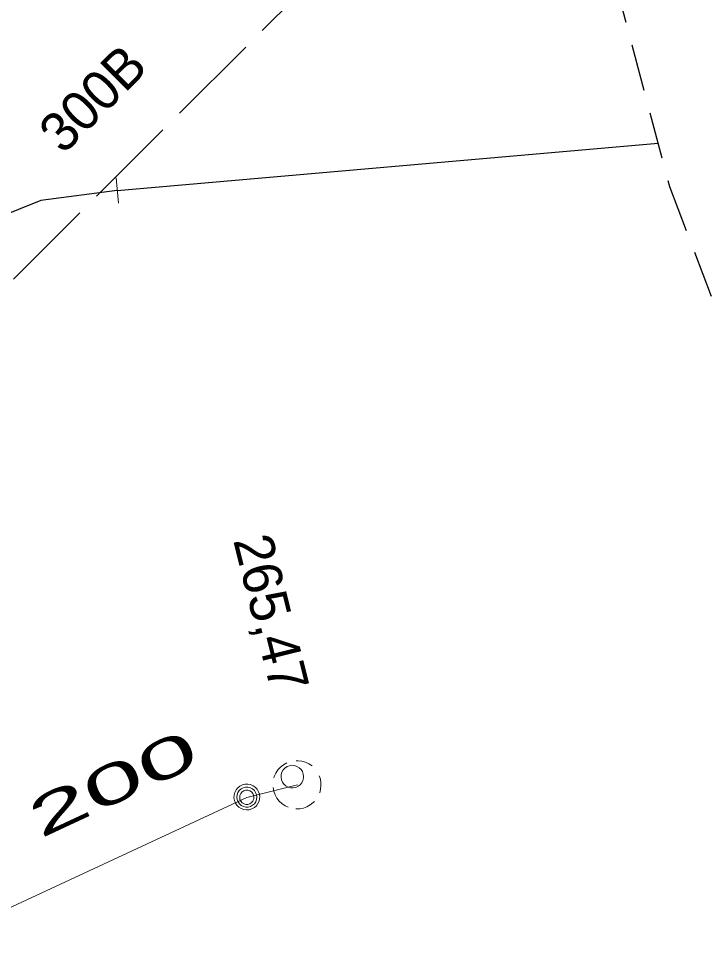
# Model space of a CAD drawing. Extents: x -732074 to -731966, y -1048695 to -1047982.
# Drawn here: x -732034.06 to -732020.02, y -1048482.15 to -1048462.87 of the extents above; entities that cross this region are included whole.
import ezdxf

# ---------------------------------------------------------------- set-up
doc = ezdxf.new("R2010")
doc.units = 0
doc.header["$LTSCALE"] = 0.32
doc.linetypes.add('LONG_DASHED', pattern=[7.5, 6, -1.5])
doc.linetypes.add('MEDIUM_DASHED', pattern=[4.5, 3, -1.5])
doc.layers.add('1', color=7, linetype='Continuous')
for name, color, linetype, lineweight in [('18', 7, 'Continuous', 13), ('20', 7, 'Continuous', 13), ('49', 7, 'Continuous', 13), ('63', 7, 'MEDIUM_DASHED', 25), ('8', 7, 'Continuous', 13)]:
    doc.layers.add(name, color=color, linetype=linetype, lineweight=lineweight)

msp = doc.modelspace()

# ---------------------------------------------------------------- linework, layer by layer
at = {"layer": '18'}
for points in [[(-732028.583, -1048478.109), (-732028.649, -1048478.148), (-732028.71, -1048478.196), (-732028.762, -1048478.252), (-732028.804, -1048478.316), (-732028.836, -1048478.387), (-732028.845, -1048478.412)], [(-732028.064, -1048478.171), (-732028.127, -1048478.129), (-732028.197, -1048478.096), (-732028.271, -1048478.073), (-732028.347, -1048478.064), (-732028.388, -1048478.063)], [(-732027.908, -1048478.721), (-732027.889, -1048478.647), (-732027.881, -1048478.571), (-732027.884, -1048478.494), (-732027.9, -1048478.419), (-732027.916, -1048478.371)], [(-732028.862, -1048478.615), (-732028.848, -1048478.69), (-732028.821, -1048478.763), (-732028.784, -1048478.829), (-732028.736, -1048478.89), (-732028.68, -1048478.942), (-732028.616, -1048478.985), (-732028.553, -1048479.015)], [(-732028.394, -1048479.049), (-732028.317, -1048479.046), (-732028.242, -1048479.032), (-732028.169, -1048479.005), (-732028.102, -1048478.968), (-732028.042, -1048478.921), (-732028.016, -1048478.896)]]:
    msp.add_lwpolyline(points, dxfattribs=at)
for points in [[(-732028.238, -1048478.389), (-732028.244, -1048478.337), (-732028.262, -1048478.287), (-732028.29, -1048478.243), (-732028.328, -1048478.206), (-732028.373, -1048478.179), (-732028.423, -1048478.163), (-732028.475, -1048478.158), (-732028.527, -1048478.165), (-732028.576, -1048478.184), (-732028.62, -1048478.214), (-732028.655, -1048478.253), (-732028.681, -1048478.298), (-732028.696, -1048478.349), (-732028.699, -1048478.401), (-732028.691, -1048478.453), (-732028.67, -1048478.501), (-732028.64, -1048478.544), (-732028.6, -1048478.579), (-732028.554, -1048478.603), (-732028.503, -1048478.617), (-732028.451, -1048478.619), (-732028.399, -1048478.609), (-732028.351, -1048478.587), (-732028.309, -1048478.555), (-732028.276, -1048478.515), (-732028.252, -1048478.468), (-732028.24, -1048478.417)], [(-732029.135, -1048478.807), (-732029.141, -1048478.751), (-732029.157, -1048478.698), (-732029.186, -1048478.649), (-732029.225, -1048478.608), (-732029.271, -1048478.576), (-732029.323, -1048478.554), (-732029.378, -1048478.543), (-732029.434, -1048478.545), (-732029.489, -1048478.558), (-732029.539, -1048478.583), (-732029.584, -1048478.618), (-732029.62, -1048478.661), (-732029.645, -1048478.711), (-732029.66, -1048478.766), (-732029.663, -1048478.822), (-732029.654, -1048478.877), (-732029.633, -1048478.93), (-732029.602, -1048478.976), (-732029.561, -1048479.015), (-732029.514, -1048479.045), (-732029.461, -1048479.064), (-732029.405, -1048479.071), (-732029.348, -1048479.067), (-732029.294, -1048479.05), (-732029.245, -1048479.023), (-732029.204, -1048478.985), (-732029.171, -1048478.94), (-732029.147, -1048478.889), (-732029.136, -1048478.834)], [(-732029.194, -1048478.81), (-732029.2, -1048478.761), (-732029.218, -1048478.715), (-732029.245, -1048478.674), (-732029.282, -1048478.641), (-732029.326, -1048478.619), (-732029.375, -1048478.607), (-732029.424, -1048478.607), (-732029.472, -1048478.619), (-732029.516, -1048478.642), (-732029.553, -1048478.675), (-732029.581, -1048478.716), (-732029.598, -1048478.763), (-732029.603, -1048478.812), (-732029.597, -1048478.861), (-732029.579, -1048478.907), (-732029.551, -1048478.947), (-732029.514, -1048478.98), (-732029.47, -1048479.002), (-732029.421, -1048479.014), (-732029.372, -1048479.013), (-732029.324, -1048479.001), (-732029.281, -1048478.977), (-732029.244, -1048478.944), (-732029.216, -1048478.903), (-732029.2, -1048478.856)], [(-732029.253, -1048478.814), (-732029.259, -1048478.772), (-732029.276, -1048478.734), (-732029.304, -1048478.703), (-732029.338, -1048478.68), (-732029.379, -1048478.669), (-732029.421, -1048478.669), (-732029.461, -1048478.681), (-732029.495, -1048478.704), (-732029.522, -1048478.736), (-732029.539, -1048478.774), (-732029.544, -1048478.815), (-732029.539, -1048478.857), (-732029.521, -1048478.894), (-732029.493, -1048478.926), (-732029.456, -1048478.948), (-732029.417, -1048478.959), (-732029.375, -1048478.958), (-732029.335, -1048478.945), (-732029.301, -1048478.922), (-732029.274, -1048478.889), (-732029.258, -1048478.851)]]:
    msp.add_lwpolyline(points, close=True, dxfattribs=at)
at = {"layer": '20', "linetype": 'LONG_DASHED'}
msp.add_line((-732035.87, -1048469.9), (-732026.27, -1048460.3), dxfattribs=at)
msp.add_line((-732035.87, -1048469.9), (-732026.27, -1048460.3), dxfattribs=at)
at = {"layer": '49'}
for p, q in [((-732028.359, -1048478.56), (-732029.399, -1048478.82)), ((-732028.359, -1048478.56), (-732029.399, -1048478.82)), ((-732029.399, -1048478.82), (-732035.513, -1048481.657)), ((-732029.399, -1048478.82), (-732035.513, -1048481.657))]:
    msp.add_line(p, q, dxfattribs=at)
at = {"layer": '63'}
msp.add_lwpolyline([(-731986.533, -1048110.659), (-732043.346, -1048381.295), (-732020.748, -1048466.307), (-731967.071, -1048608.112)], dxfattribs=at)
at = {"layer": '8', "lineweight": 25}
msp.add_line((-732032.05, -1048466.39), (-732020.983, -1048465.423), dxfattribs=at)
at = {"layer": '8'}
msp.add_line((-732032.072, -1048466.131), (-732032.028, -1048466.646), dxfattribs=at)
at = {"layer": '8', "lineweight": 25}
msp.add_lwpolyline([(-732032.05, -1048466.39), (-732033.616, -1048466.591), (-732038.16, -1048468.42), (-732043.974, -1048470.885)], dxfattribs=at)

# ---------------------------------------------------------------- texts
at = {"layer": '1'}
for s, rotation, p in [('300B', 45, (-732033.156, -1048465.668)), ('265,47', 284, (-732029.68, -1048473.548))]:
    msp.add_text(s, height=0.8, rotation=rotation, dxfattribs=at).set_placement(p)
at = {"layer": '1', "width": 2.05}
msp.add_text('200 ', height=0.8, rotation=25, dxfattribs=at).set_placement((-732033.626, -1048479.664))

doc.saveas('drawing.dxf')
